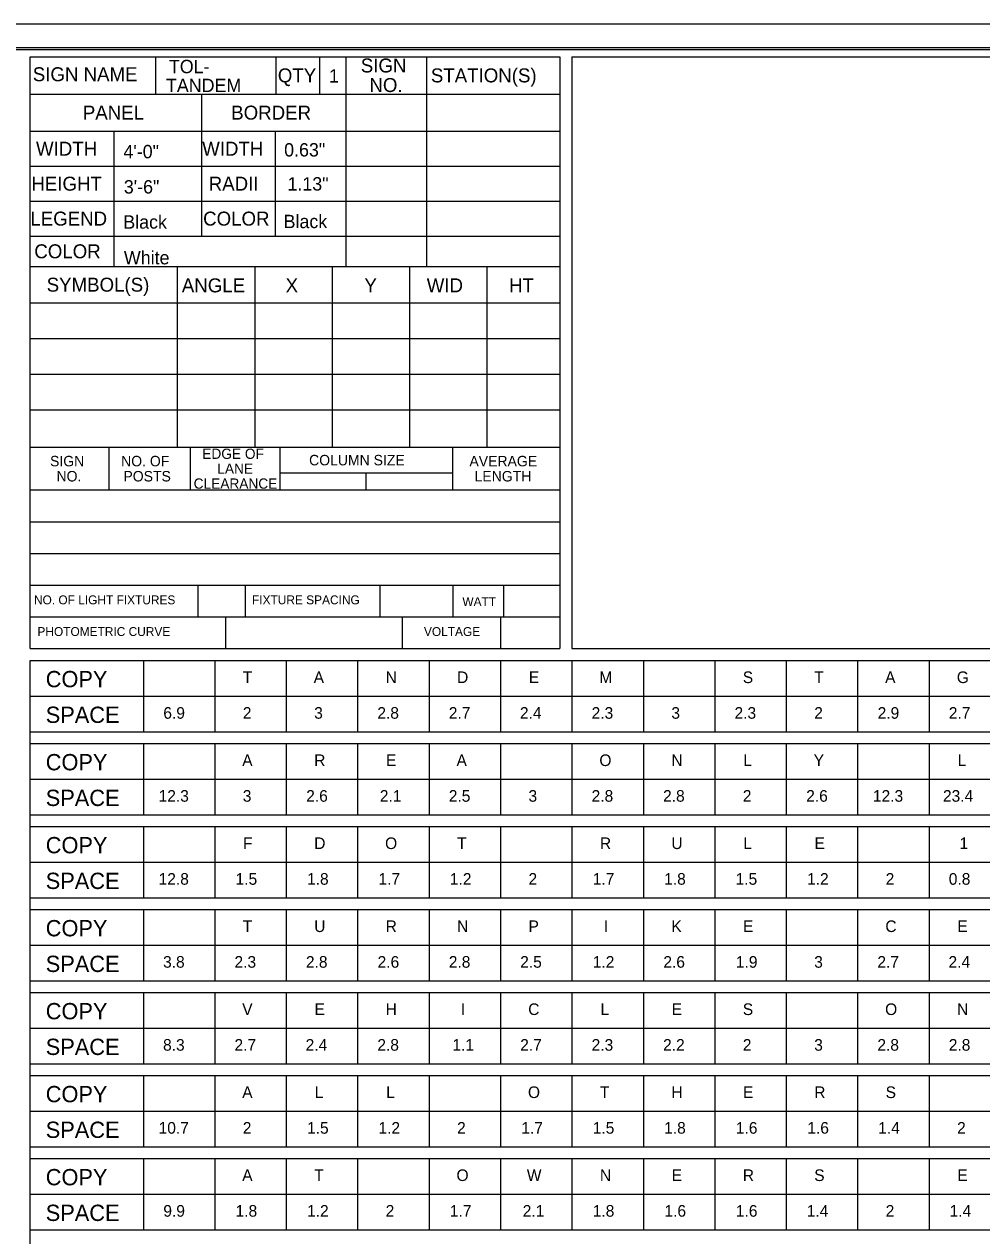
# Model space of a CAD drawing. Extents: x 17890628 to 17890817, y 17897493 to 17897992.
# Drawn here: x 17890736.6 to 17890776.9, y 17897545.7 to 17897596.8 of the extents above; entities that cross this region are included whole.
import ezdxf

# ---------------------------------------------------------------- set-up
doc = ezdxf.new("R2010")
doc.units = 0
for name, color, linetype in [('GSSign', 7, 'Continuous'), ('PlotBorder_dp', 7, 'Continuous'), ('SheetBorder_dp', 7, 'Continuous'), ('SheetLinesMisc1_dp', 7, 'Continuous'), ('SheetLinesMisc2_dp', 7, 'Continuous'), ('TextMinor', 7, 'Continuous')]:
    doc.layers.add(name, color=color, linetype=linetype)

msp = doc.modelspace()

# ---------------------------------------------------------------- linework, layer by layer
at = {"layer": 'PlotBorder_dp'}
msp.add_lwpolyline([(17890655.57, 17897492.839), (17890817.319, 17897492.839), (17890817.319, 17897596.75), (17890655.57, 17897596.75)], close=True, dxfattribs=at)
at = {"layer": 'SheetBorder_dp'}
msp.add_line((17890660.962, 17897595.77), (17890811.928, 17897595.77), dxfattribs=at)
at = {"layer": 'SheetLinesMisc1_dp'}
for p, q in [((17890742.118, 17897593.81), (17890742.118, 17897595.379)), ((17890747.165, 17897595.379), (17890747.165, 17897593.81)), ((17890749.018, 17897595.379), (17890749.018, 17897593.81)), ((17890750.122, 17897595.379), (17890750.122, 17897586.544)), ((17890753.517, 17897595.379), (17890753.517, 17897586.544)), ((17890736.824, 17897593.81), (17890759.135, 17897593.81)), ((17890744.035, 17897593.81), (17890744.035, 17897587.809)), ((17890736.824, 17897592.242), (17890759.135, 17897592.242)), ((17890740.35, 17897592.242), (17890740.35, 17897586.544)), ((17890747.146, 17897592.226), (17890747.146, 17897587.809)), ((17890736.824, 17897590.77), (17890759.135, 17897590.77)), ((17890736.824, 17897589.297), (17890759.135, 17897589.297)), ((17890736.824, 17897587.825), (17890759.135, 17897587.825)), ((17890736.824, 17897586.544), (17890759.135, 17897586.544)), ((17890743.02, 17897586.544), (17890743.02, 17897578.926)), ((17890746.28, 17897586.544), (17890746.28, 17897578.926)), ((17890749.54, 17897586.544), (17890749.54, 17897578.926)), ((17890752.8, 17897586.515), (17890752.8, 17897578.926)), ((17890756.06, 17897586.515), (17890756.06, 17897578.926)), ((17890736.829, 17897585.012), (17890759.135, 17897585.012)), ((17890736.829, 17897583.508), (17890759.135, 17897583.508)), ((17890736.829, 17897582.005), (17890759.135, 17897582.005)), ((17890736.829, 17897580.501), (17890759.135, 17897580.501)), ((17890736.824, 17897578.926), (17890759.135, 17897578.926)), ((17890740.135, 17897578.926), (17890740.135, 17897577.129)), ((17890743.557, 17897578.926), (17890743.557, 17897577.129)), ((17890747.335, 17897578.926), (17890747.335, 17897577.129)), ((17890754.611, 17897578.926), (17890754.611, 17897577.129)), ((17890747.335, 17897577.848), (17890754.606, 17897577.848)), ((17890750.97, 17897577.848), (17890750.97, 17897577.129)), ((17890736.824, 17897577.129), (17890759.135, 17897577.129)), ((17890736.824, 17897575.794), (17890759.135, 17897575.794)), ((17890736.824, 17897574.458), (17890759.135, 17897574.458)), ((17890736.824, 17897573.122), (17890759.135, 17897573.122)), ((17890736.824, 17897571.787), (17890759.135, 17897571.787)), ((17890741.588, 17897569.94), (17890741.588, 17897566.934)), ((17890744.599, 17897569.94), (17890744.599, 17897566.934)), ((17890747.61, 17897569.94), (17890747.61, 17897566.934)), ((17890750.62, 17897569.94), (17890750.62, 17897566.934)), ((17890753.63, 17897569.94), (17890753.63, 17897566.934)), ((17890756.64, 17897569.94), (17890756.64, 17897566.934)), ((17890759.651, 17897569.94), (17890759.651, 17897566.934)), ((17890762.661, 17897569.94), (17890762.661, 17897566.934)), ((17890765.671, 17897569.94), (17890765.671, 17897566.934)), ((17890768.681, 17897569.94), (17890768.681, 17897566.934)), ((17890771.692, 17897569.94), (17890771.692, 17897566.934)), ((17890774.703, 17897569.94), (17890774.703, 17897566.934)), ((17890736.825, 17897568.436), (17890810.827, 17897568.437)), ((17890736.825, 17897566.934), (17890810.827, 17897566.934)), ((17890736.825, 17897566.443), (17890810.827, 17897566.443)), ((17890741.588, 17897566.443), (17890741.588, 17897563.437)), ((17890744.599, 17897566.443), (17890744.599, 17897563.437)), ((17890747.61, 17897566.443), (17890747.61, 17897563.437)), ((17890750.62, 17897566.443), (17890750.62, 17897563.437)), ((17890753.63, 17897566.443), (17890753.63, 17897563.437)), ((17890756.64, 17897566.443), (17890756.64, 17897563.437)), ((17890759.651, 17897566.443), (17890759.651, 17897563.437)), ((17890762.661, 17897566.443), (17890762.661, 17897563.437)), ((17890765.671, 17897566.443), (17890765.671, 17897563.437)), ((17890768.681, 17897566.443), (17890768.681, 17897563.437)), ((17890771.692, 17897566.443), (17890771.692, 17897563.437)), ((17890774.703, 17897566.443), (17890774.703, 17897563.437)), ((17890736.825, 17897564.94), (17890810.827, 17897564.94)), ((17890736.825, 17897563.437), (17890810.827, 17897563.437)), ((17890736.825, 17897562.947), (17890810.827, 17897562.947)), ((17890741.588, 17897562.947), (17890741.588, 17897559.94)), ((17890744.599, 17897562.947), (17890744.599, 17897559.94)), ((17890747.61, 17897562.947), (17890747.61, 17897559.94)), ((17890750.62, 17897562.947), (17890750.62, 17897559.94)), ((17890753.63, 17897562.947), (17890753.63, 17897559.94)), ((17890756.64, 17897562.947), (17890756.64, 17897559.94)), ((17890759.651, 17897562.947), (17890759.651, 17897559.94)), ((17890762.661, 17897562.947), (17890762.661, 17897559.94)), ((17890765.671, 17897562.947), (17890765.671, 17897559.94)), ((17890768.681, 17897562.947), (17890768.681, 17897559.94)), ((17890771.692, 17897562.947), (17890771.692, 17897559.94)), ((17890774.703, 17897562.947), (17890774.703, 17897559.94)), ((17890736.825, 17897561.443), (17890810.827, 17897561.443)), ((17890736.825, 17897559.94), (17890810.827, 17897559.94)), ((17890736.825, 17897559.45), (17890810.827, 17897559.45)), ((17890741.588, 17897559.45), (17890741.588, 17897556.443)), ((17890744.599, 17897559.45), (17890744.599, 17897556.443)), ((17890747.61, 17897559.45), (17890747.61, 17897556.443)), ((17890750.62, 17897559.45), (17890750.62, 17897556.443)), ((17890753.63, 17897559.45), (17890753.63, 17897556.443)), ((17890756.64, 17897559.45), (17890756.64, 17897556.443)), ((17890759.651, 17897559.45), (17890759.651, 17897556.443)), ((17890762.661, 17897559.45), (17890762.661, 17897556.443)), ((17890765.671, 17897559.45), (17890765.671, 17897556.443)), ((17890768.681, 17897559.45), (17890768.681, 17897556.443)), ((17890771.692, 17897559.45), (17890771.692, 17897556.443)), ((17890774.703, 17897559.45), (17890774.703, 17897556.443)), ((17890736.825, 17897557.947), (17890810.827, 17897557.947)), ((17890736.825, 17897556.443), (17890810.827, 17897556.443)), ((17890736.825, 17897555.953), (17890810.827, 17897555.953)), ((17890741.588, 17897555.953), (17890741.588, 17897552.947)), ((17890744.599, 17897555.953), (17890744.599, 17897552.947)), ((17890747.61, 17897555.953), (17890747.61, 17897552.947)), ((17890750.62, 17897555.953), (17890750.62, 17897552.947)), ((17890753.63, 17897555.953), (17890753.63, 17897552.947)), ((17890756.64, 17897555.953), (17890756.64, 17897552.947)), ((17890759.651, 17897555.953), (17890759.651, 17897552.947)), ((17890762.661, 17897555.953), (17890762.661, 17897552.947)), ((17890765.671, 17897555.953), (17890765.671, 17897552.947)), ((17890768.681, 17897555.953), (17890768.681, 17897552.947)), ((17890771.692, 17897555.953), (17890771.692, 17897552.947)), ((17890774.703, 17897555.953), (17890774.703, 17897552.947)), ((17890736.825, 17897554.451), (17890810.827, 17897554.451)), ((17890736.825, 17897552.947), (17890810.827, 17897552.947)), ((17890736.825, 17897552.457), (17890810.827, 17897552.457)), ((17890741.588, 17897552.457), (17890741.588, 17897549.451)), ((17890744.599, 17897552.457), (17890744.599, 17897549.451)), ((17890747.61, 17897552.457), (17890747.61, 17897549.451)), ((17890750.62, 17897552.457), (17890750.62, 17897549.451)), ((17890753.63, 17897552.457), (17890753.63, 17897549.451)), ((17890756.64, 17897552.457), (17890756.64, 17897549.451)), ((17890759.651, 17897552.457), (17890759.651, 17897549.451)), ((17890762.661, 17897552.457), (17890762.661, 17897549.451)), ((17890765.671, 17897552.457), (17890765.671, 17897549.451)), ((17890768.681, 17897552.457), (17890768.681, 17897549.451)), ((17890771.692, 17897552.457), (17890771.692, 17897549.451)), ((17890774.703, 17897552.457), (17890774.703, 17897549.451)), ((17890736.825, 17897550.953), (17890810.827, 17897550.954)), ((17890736.825, 17897549.451), (17890810.827, 17897549.451)), ((17890736.825, 17897548.961), (17890810.827, 17897548.961)), ((17890741.588, 17897548.961), (17890741.588, 17897545.954)), ((17890744.599, 17897548.961), (17890744.599, 17897545.954)), ((17890747.61, 17897548.961), (17890747.61, 17897545.954)), ((17890750.62, 17897548.961), (17890750.62, 17897545.954)), ((17890753.63, 17897548.961), (17890753.63, 17897545.954)), ((17890756.64, 17897548.961), (17890756.64, 17897545.954)), ((17890759.651, 17897548.961), (17890759.651, 17897545.954)), ((17890762.661, 17897548.961), (17890762.661, 17897545.954)), ((17890765.671, 17897548.961), (17890765.671, 17897545.954)), ((17890768.681, 17897548.961), (17890768.681, 17897545.954)), ((17890771.692, 17897548.961), (17890771.692, 17897545.954)), ((17890774.703, 17897548.961), (17890774.703, 17897545.954)), ((17890736.825, 17897547.457), (17890810.827, 17897547.457)), ((17890736.825, 17897545.954), (17890810.827, 17897545.954))]:
    msp.add_line(p, q, dxfattribs=at)
at = {"layer": 'SheetLinesMisc2_dp'}
for p, q in [((17890661.083, 17897595.691), (17890811.539, 17897595.691)), ((17890736.824, 17897595.379), (17890759.135, 17897595.379)), ((17890736.824, 17897570.451), (17890736.824, 17897595.379)), ((17890736.824, 17897595.379), (17890759.135, 17897595.379)), ((17890759.135, 17897595.379), (17890759.135, 17897570.451)), ((17890759.648, 17897595.379), (17890810.82, 17897595.379)), ((17890759.648, 17897595.379), (17890759.648, 17897570.453)), ((17890736.824, 17897573.122), (17890759.13, 17897573.122)), ((17890743.882, 17897573.122), (17890743.882, 17897571.786)), ((17890745.875, 17897573.122), (17890745.875, 17897571.786)), ((17890751.55, 17897573.122), (17890751.55, 17897571.786)), ((17890754.636, 17897573.122), (17890754.636, 17897571.786)), ((17890756.766, 17897573.122), (17890756.766, 17897571.786)), ((17890736.824, 17897571.786), (17890759.13, 17897571.786)), ((17890745.052, 17897571.786), (17890745.052, 17897570.451)), ((17890752.495, 17897571.786), (17890752.495, 17897570.451)), ((17890756.637, 17897571.786), (17890756.637, 17897570.451)), ((17890736.824, 17897570.451), (17890759.13, 17897570.451)), ((17890736.824, 17897570.451), (17890759.135, 17897570.451)), ((17890759.648, 17897570.453), (17890810.82, 17897570.453)), ((17890736.825, 17897549.452), (17890736.825, 17897569.94)), ((17890736.825, 17897569.94), (17890810.827, 17897569.94)), ((17890736.825, 17897502.398), (17890736.825, 17897569.94))]:
    msp.add_line(p, q, dxfattribs=at)

# ---------------------------------------------------------------- texts
at = {"layer": 'GSSign'}
for s, height, p in [('TOL-', 0.5624, (17890742.665, 17897594.688)), ('TANDEM', 0.5624, (17890742.54, 17897593.892)), ('1', 0.562, (17890749.414, 17897594.294)), ('4\'-0"', 0.5624, (17890740.749, 17897591.103)), ('0.63"', 0.5624, (17890747.522, 17897591.178)), ('1.13"', 0.5624, (17890747.662, 17897589.744)), ('3\'-6"', 0.5624, (17890740.765, 17897589.619)), ('Black', 0.5624, (17890747.499, 17897588.16)), ('Black', 0.5624, (17890740.743, 17897588.138)), ('White', 0.5624, (17890740.768, 17897586.634)), ('T', 0.49, (17890745.779, 17897568.994)), ('A', 0.49, (17890748.766, 17897568.994)), ('N', 0.49, (17890751.799, 17897568.994)), ('D', 0.49, (17890754.81, 17897568.994)), ('E', 0.49, (17890757.832, 17897568.994)), ('M', 0.49, (17890760.807, 17897568.994)), ('S', 0.49, (17890766.851, 17897568.994)), ('T', 0.49, (17890769.862, 17897568.994)), ('A', 0.49, (17890772.849, 17897568.994)), ('G', 0.49, (17890775.871, 17897568.994)), ('6.9', 0.4902, (17890742.43, 17897567.491)), ('2', 0.49, (17890745.779, 17897567.491)), ('3', 0.49, (17890748.789, 17897567.491)), ('2.8', 0.4902, (17890751.449, 17897567.491)), ('2.7', 0.4902, (17890754.46, 17897567.491)), ('2.4', 0.4902, (17890757.458, 17897567.491)), ('2.3', 0.4902, (17890760.48, 17897567.491)), ('3', 0.49, (17890763.841, 17897567.491)), ('2.3', 0.4902, (17890766.501, 17897567.491)), ('2', 0.49, (17890769.862, 17897567.491)), ('2.9', 0.4902, (17890772.534, 17897567.491)), ('2.7', 0.4902, (17890775.532, 17897567.491)), ('A', 0.49, (17890745.755, 17897565.498)), ('R', 0.49, (17890748.789, 17897565.498)), ('E', 0.49, (17890751.811, 17897565.498)), ('A', 0.49, (17890754.786, 17897565.498)), ('O', 0.49, (17890760.807, 17897565.498)), ('N', 0.49, (17890763.841, 17897565.498)), ('L', 0.49, (17890766.875, 17897565.498)), ('Y', 0.49, (17890769.838, 17897565.498)), ('L', 0.49, (17890775.906, 17897565.498)), ('12.3', 0.4902, (17890742.231, 17897563.995)), ('3', 0.49, (17890745.779, 17897563.995)), ('2.6', 0.4902, (17890748.451, 17897563.995)), ('2.1', 0.4902, (17890751.554, 17897563.995)), ('2.5', 0.4902, (17890754.46, 17897563.995)), ('3', 0.49, (17890757.82, 17897563.995)), ('2.8', 0.4902, (17890760.48, 17897563.995)), ('2.8', 0.4902, (17890763.491, 17897563.995)), ('2', 0.49, (17890766.851, 17897563.995)), ('2.6', 0.4902, (17890769.523, 17897563.995)), ('12.3', 0.4902, (17890772.335, 17897563.995)), ('23.4', 0.4902, (17890775.287, 17897563.995)), ('F', 0.49, (17890745.79, 17897562.001)), ('D', 0.49, (17890748.789, 17897562.001)), ('O', 0.49, (17890751.776, 17897562.001)), ('T', 0.49, (17890754.81, 17897562.001)), ('R', 0.49, (17890760.83, 17897562.001)), ('U', 0.49, (17890763.841, 17897562.001)), ('L', 0.49, (17890766.875, 17897562.001)), ('E', 0.49, (17890769.873, 17897562.001)), ('1', 0.49, (17890775.987, 17897562.001)), ('12.8', 0.4902, (17890742.231, 17897560.498)), ('1.5', 0.4902, (17890745.475, 17897560.498)), ('1.8', 0.4902, (17890748.486, 17897560.498)), ('1.7', 0.4902, (17890751.496, 17897560.498)), ('1.2', 0.4902, (17890754.506, 17897560.498)), ('2', 0.49, (17890757.82, 17897560.498)), ('1.7', 0.4902, (17890760.527, 17897560.498)), ('1.8', 0.4902, (17890763.537, 17897560.498)), ('1.5', 0.4902, (17890766.548, 17897560.498)), ('1.2', 0.4902, (17890769.558, 17897560.498)), ('2', 0.49, (17890772.872, 17897560.498)), ('0.8', 0.4902, (17890775.532, 17897560.498)), ('T', 0.49, (17890745.779, 17897558.505)), ('U', 0.49, (17890748.789, 17897558.505)), ('R', 0.49, (17890751.799, 17897558.505)), ('N', 0.49, (17890754.81, 17897558.505)), ('P', 0.49, (17890757.82, 17897558.505)), ('I', 0.49, (17890760.994, 17897558.505)), ('K', 0.49, (17890763.841, 17897558.505)), ('E', 0.49, (17890766.863, 17897558.505)), ('C', 0.49, (17890772.86, 17897558.505)), ('E', 0.49, (17890775.894, 17897558.505)), ('3.8', 0.4902, (17890742.418, 17897557.002)), ('2.3', 0.4902, (17890745.428, 17897557.002)), ('2.8', 0.4902, (17890748.439, 17897557.002)), ('2.6', 0.4902, (17890751.461, 17897557.002)), ('2.8', 0.4902, (17890754.46, 17897557.002)), ('2.5', 0.4902, (17890757.47, 17897557.002)), ('1.2', 0.4902, (17890760.527, 17897557.002)), ('2.6', 0.4902, (17890763.502, 17897557.002)), ('1.9', 0.4902, (17890766.559, 17897557.002)), ('3', 0.49, (17890769.862, 17897557.002)), ('2.7', 0.4902, (17890772.522, 17897557.002)), ('2.4', 0.4902, (17890775.521, 17897557.002)), ('V', 0.49, (17890745.755, 17897555.009)), ('E', 0.49, (17890748.801, 17897555.009)), ('H', 0.49, (17890751.799, 17897555.009)), ('I', 0.49, (17890754.973, 17897555.009)), ('C', 0.49, (17890757.808, 17897555.009)), ('L', 0.49, (17890760.854, 17897555.009)), ('E', 0.49, (17890763.852, 17897555.009)), ('S', 0.49, (17890766.851, 17897555.009)), ('O', 0.49, (17890772.849, 17897555.009)), ('N', 0.49, (17890775.882, 17897555.009)), ('8.3', 0.4902, (17890742.418, 17897553.506)), ('2.7', 0.4902, (17890745.428, 17897553.506)), ('2.4', 0.4902, (17890748.427, 17897553.506)), ('2.8', 0.4902, (17890751.449, 17897553.506)), ('1.1', 0.4902, (17890754.611, 17897553.506)), ('2.7', 0.4902, (17890757.47, 17897553.506)), ('2.3', 0.4902, (17890760.48, 17897553.506)), ('2.2', 0.4902, (17890763.491, 17897553.506)), ('2', 0.49, (17890766.851, 17897553.506)), ('3', 0.49, (17890769.862, 17897553.506)), ('2.8', 0.4902, (17890772.522, 17897553.506)), ('2.8', 0.4902, (17890775.532, 17897553.506)), ('A', 0.49, (17890745.755, 17897551.512)), ('L', 0.49, (17890748.812, 17897551.512)), ('L', 0.49, (17890751.823, 17897551.512)), ('O', 0.49, (17890757.797, 17897551.512)), ('T', 0.49, (17890760.83, 17897551.512)), ('H', 0.49, (17890763.841, 17897551.512)), ('E', 0.49, (17890766.863, 17897551.512)), ('R', 0.49, (17890769.862, 17897551.512)), ('S', 0.49, (17890772.872, 17897551.512)), ('10.7', 0.4902, (17890742.231, 17897550.01)), ('2', 0.49, (17890745.779, 17897550.01)), ('1.5', 0.4902, (17890748.486, 17897550.01)), ('1.2', 0.4902, (17890751.496, 17897550.01)), ('2', 0.49, (17890754.81, 17897550.01)), ('1.7', 0.4902, (17890757.517, 17897550.01)), ('1.5', 0.4902, (17890760.527, 17897550.01)), ('1.8', 0.4902, (17890763.537, 17897550.01)), ('1.6', 0.4902, (17890766.559, 17897550.01)), ('1.6', 0.4902, (17890769.57, 17897550.01)), ('1.4', 0.4902, (17890772.557, 17897550.01)), ('2', 0.49, (17890775.882, 17897550.01)), ('A', 0.49, (17890745.755, 17897548.016)), ('T', 0.49, (17890748.789, 17897548.016)), ('O', 0.49, (17890754.786, 17897548.016)), ('W', 0.49, (17890757.75, 17897548.016)), ('N', 0.49, (17890760.83, 17897548.016)), ('E', 0.49, (17890763.852, 17897548.016)), ('R', 0.49, (17890766.851, 17897548.016)), ('S', 0.49, (17890769.862, 17897548.016)), ('E', 0.49, (17890775.894, 17897548.016)), ('9.9', 0.4902, (17890742.43, 17897546.513)), ('1.8', 0.4902, (17890745.475, 17897546.513)), ('1.2', 0.4902, (17890748.486, 17897546.513)), ('2', 0.49, (17890751.799, 17897546.513)), ('1.7', 0.4902, (17890754.506, 17897546.513)), ('2.1', 0.4902, (17890757.575, 17897546.513)), ('1.8', 0.4902, (17890760.527, 17897546.513)), ('1.6', 0.4902, (17890763.549, 17897546.513)), ('1.6', 0.4902, (17890766.559, 17897546.513)), ('1.4', 0.4902, (17890769.546, 17897546.513)), ('2', 0.49, (17890772.872, 17897546.513)), ('1.4', 0.4902, (17890775.567, 17897546.513))]:
    msp.add_text(s, height=height, dxfattribs=at).set_placement(p)
at = {"layer": 'TextMinor'}
for s, height, p in [('SIGN NAME', 0.5882, (17890736.928, 17897594.349)), ('QTY', 0.5882, (17890747.256, 17897594.3)), ('SIGN', 0.5882, (17890750.752, 17897594.718)), ('STATION(S)', 0.5882, (17890753.706, 17897594.3)), ('NO.', 0.5882, (17890751.116, 17897593.895)), ('PANEL', 0.5882, (17890739.038, 17897592.732)), ('BORDER', 0.5882, (17890745.291, 17897592.732)), ('WIDTH', 0.5882, (17890737.064, 17897591.212)), ('WIDTH', 0.5882, (17890744.068, 17897591.212)), ('HEIGHT', 0.5882, (17890736.868, 17897589.739)), ('RADII', 0.5882, (17890744.343, 17897589.739)), ('LEGEND', 0.5882, (17890736.826, 17897588.267)), ('COLOR', 0.5882, (17890744.108, 17897588.267)), ('COLOR', 0.5882, (17890736.993, 17897586.89)), ('SYMBOL(S)', 0.5882, (17890737.514, 17897585.484)), ('ANGLE', 0.5882, (17890743.21, 17897585.455)), ('X', 0.588, (17890747.584, 17897585.455)), ('Y', 0.588, (17890750.905, 17897585.455)), ('WID', 0.5882, (17890753.532, 17897585.455)), ('HT', 0.5882, (17890756.998, 17897585.455)), ('SIGN', 0.4411, (17890737.657, 17897578.125)), ('NO. OF', 0.4411, (17890740.65, 17897578.125)), ('EDGE OF', 0.4313, (17890744.072, 17897578.439)), ('COLUMN SIZE', 0.44113, (17890748.573, 17897578.166)), ('AVERAGE', 0.4411, (17890755.331, 17897578.125)), ('LANE', 0.4313, (17890744.705, 17897577.812)), ('NO.', 0.4411, (17890737.929, 17897577.488)), ('POSTS', 0.4411, (17890740.749, 17897577.488)), ('CLEARANCE', 0.4313, (17890743.709, 17897577.184)), ('LENGTH', 0.4411, (17890755.548, 17897577.488)), ('NO. OF LIGHT FIXTURES', 0.37485, (17890736.978, 17897572.312)), ('FIXTURE SPACING', 0.37485, (17890746.168, 17897572.312)), ('WATT', 0.3749, (17890755.034, 17897572.237)), ('PHOTOMETRIC CURVE', 0.37485, (17890737.125, 17897570.977)), ('VOLTAGE', 0.3749, (17890753.414, 17897570.976)), ('COPY', 0.6862, (17890737.474, 17897568.819)), ('SPACE', 0.6862, (17890737.474, 17897567.315)), ('COPY', 0.6862, (17890737.474, 17897565.319)), ('SPACE', 0.6862, (17890737.474, 17897563.815)), ('COPY', 0.6862, (17890737.474, 17897561.823)), ('SPACE', 0.6862, (17890737.474, 17897560.319)), ('COPY', 0.6862, (17890737.474, 17897558.325)), ('SPACE', 0.6862, (17890737.474, 17897556.822)), ('COPY', 0.6862, (17890737.474, 17897554.83)), ('SPACE', 0.6862, (17890737.474, 17897553.326)), ('COPY', 0.6862, (17890737.474, 17897551.336)), ('SPACE', 0.6862, (17890737.474, 17897549.832)), ('COPY', 0.6862, (17890737.474, 17897547.836)), ('SPACE', 0.6862, (17890737.474, 17897546.333))]:
    msp.add_text(s, height=height, dxfattribs=at).set_placement(p)

doc.saveas('drawing.dxf')
